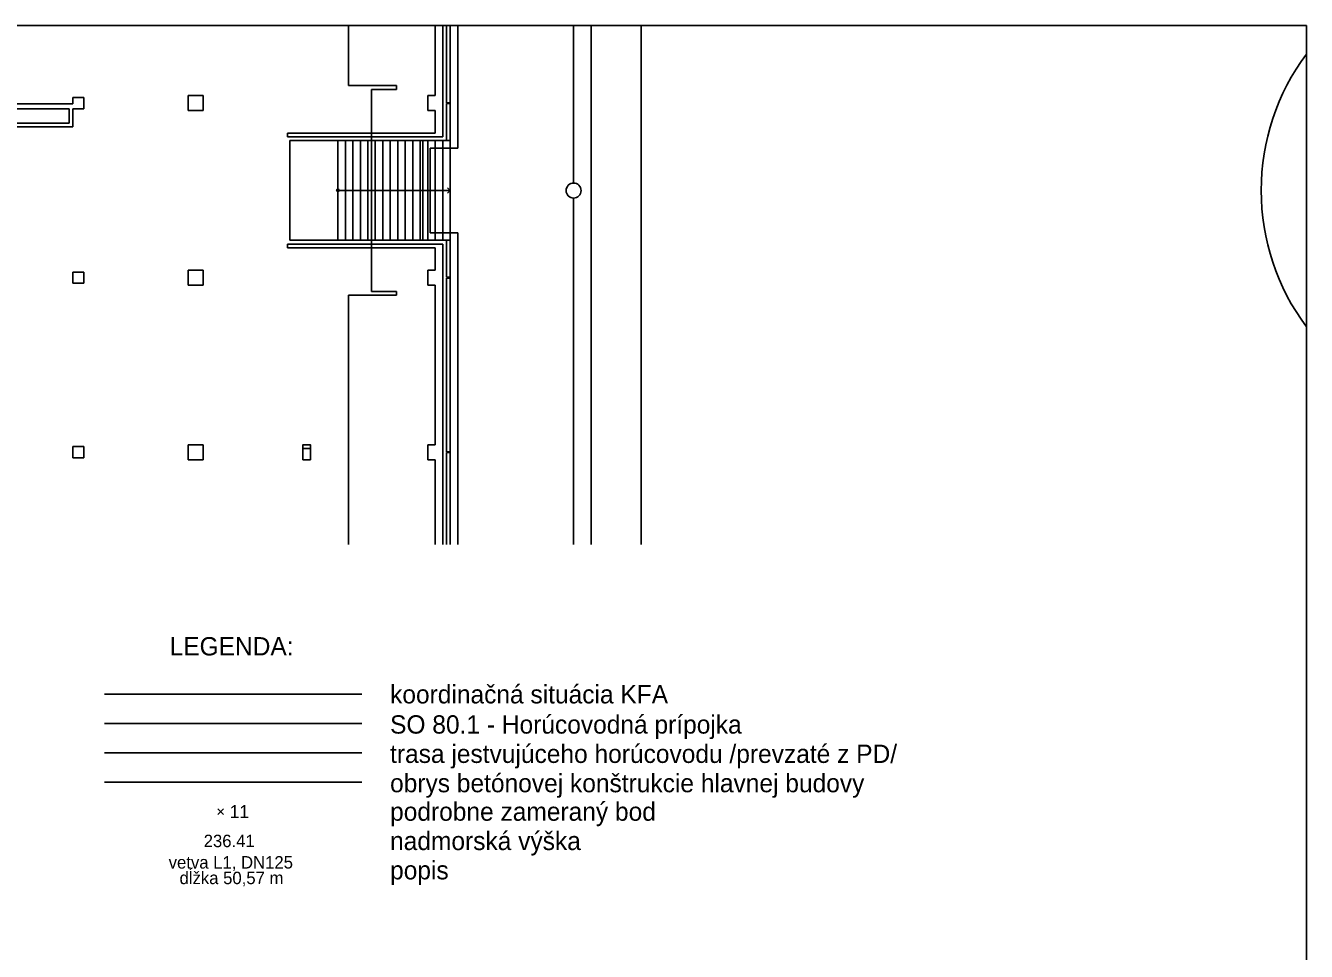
# Model space of a CAD drawing. Extents: x -263964 to -263859, y -1242287 to -1242158.
# Drawn here: x -263910.6 to -263859.3, y -1242194.9 to -1242157.8 of the extents above; entities that cross this region are included whole.
import ezdxf

# ---------------------------------------------------------------- set-up
doc = ezdxf.new("R2010")
doc.units = 0
for name, color, linetype in [('KFA_2D_SITUACIA_DSP', 7, 'Continuous'), ('KFA_BETONY_HL_B_1PP', 7, 'Continuous'), ('LEGENDA', 7, 'Continuous'), ('RAM_NA_TLAC_A3_1-250', 7, 'Continuous')]:
    doc.layers.add(name, color=color, linetype=linetype)

msp = doc.modelspace()

# ---------------------------------------------------------------- linework, layer by layer
at = {"layer": 'KFA_2D_SITUACIA_DSP'}
for p, q in [((-263897.693, -1242157.773), (-263897.693, -1242160.182)), ((-263893.618, -1242178.582), (-263893.618, -1242157.773)), ((-263893.618, -1242157.773), (-263893.618, -1242162.382)), ((-263893.618, -1242162.382), (-263893.618, -1242157.773)), ((-263893.318, -1242157.773), (-263893.318, -1242162.682)), ((-263888.673, -1242157.773), (-263888.673, -1242164.087)), ((-263887.968, -1242178.582), (-263887.968, -1242157.773)), ((-263885.968, -1242178.582), (-263885.968, -1242157.773)), ((-263897.693, -1242160.182), (-263895.768, -1242160.182)), ((-263895.768, -1242160.332), (-263896.768, -1242160.332)), ((-263896.768, -1242160.332), (-263896.768, -1242168.432)), ((-263895.768, -1242160.182), (-263895.768, -1242160.332)), ((-263900.043, -1242166.382), (-263900.043, -1242162.382)), ((-263900.043, -1242162.382), (-263893.618, -1242162.382)), ((-263898.118, -1242162.382), (-263898.118, -1242166.382)), ((-263897.818, -1242162.382), (-263897.818, -1242166.382)), ((-263897.518, -1242162.382), (-263897.518, -1242166.382)), ((-263897.218, -1242162.382), (-263897.218, -1242166.382)), ((-263896.918, -1242162.382), (-263896.918, -1242166.382)), ((-263896.618, -1242162.382), (-263896.618, -1242166.382)), ((-263896.318, -1242162.382), (-263896.318, -1242166.382)), ((-263896.018, -1242162.382), (-263896.018, -1242166.382)), ((-263895.718, -1242162.382), (-263895.718, -1242166.382)), ((-263895.418, -1242162.382), (-263895.418, -1242166.382)), ((-263895.118, -1242162.382), (-263895.118, -1242166.382)), ((-263894.818, -1242162.382), (-263894.818, -1242166.382)), ((-263893.618, -1242162.382), (-263894.718, -1242162.382)), ((-263894.718, -1242162.382), (-263894.718, -1242166.382)), ((-263894.518, -1242162.382), (-263894.518, -1242166.382)), ((-263894.218, -1242162.382), (-263894.218, -1242166.382)), ((-263893.918, -1242162.382), (-263893.918, -1242166.382)), ((-263893.618, -1242162.382), (-263893.618, -1242166.382)), ((-263893.318, -1242162.682), (-263894.418, -1242162.682)), ((-263894.418, -1242162.682), (-263894.418, -1242166.082)), ((-263898.118, -1242164.382), (-263893.618, -1242164.382)), ((-263893.618, -1242164.382), (-263893.721, -1242164.274)), ((-263893.618, -1242164.382), (-263893.721, -1242164.491)), ((-263888.673, -1242164.687), (-263888.673, -1242178.582)), ((-263894.418, -1242166.082), (-263893.318, -1242166.082)), ((-263893.318, -1242166.082), (-263893.318, -1242178.582)), ((-263893.618, -1242166.382), (-263900.043, -1242166.382)), ((-263894.718, -1242166.382), (-263893.618, -1242166.382)), ((-263893.618, -1242166.382), (-263893.618, -1242178.582)), ((-263893.618, -1242178.582), (-263893.618, -1242166.382)), ((-263895.768, -1242168.582), (-263897.693, -1242168.582)), ((-263897.693, -1242168.582), (-263897.693, -1242178.582)), ((-263896.768, -1242168.432), (-263895.768, -1242168.432)), ((-263895.768, -1242168.432), (-263895.768, -1242168.582))]:
    msp.add_line(p, q, dxfattribs=at)
for centre, radius in [((-263888.673, -1242164.387), 0.3), ((-263898.118, -1242164.382), 0.05)]:
    msp.add_circle(centre, radius, dxfattribs=at)
for start, end in [(143.329, 180), (180, 216.671)]:
    msp.add_arc((-263851.968, -1242164.382), 9.15, start, end, dxfattribs=at)
at = {"layer": 'KFA_BETONY_HL_B_1PP'}
for p, q in [((-263894.218, -1242157.773), (-263894.218, -1242160.582)), ((-263893.918, -1242157.773), (-263893.918, -1242160.582)), ((-263893.918, -1242160.582), (-263893.918, -1242157.773)), ((-263893.768, -1242157.773), (-263893.768, -1242160.867)), ((-263893.618, -1242160.867), (-263893.618, -1242157.773)), ((-263910.143, -1242160.907), (-263911.793, -1242160.907)), ((-263908.743, -1242160.907), (-263910.143, -1242160.907)), ((-263908.743, -1242160.657), (-263908.293, -1242160.657)), ((-263908.743, -1242160.907), (-263908.743, -1242160.657)), ((-263908.293, -1242160.657), (-263908.293, -1242161.107)), ((-263903.518, -1242160.582), (-263904.118, -1242160.582)), ((-263904.118, -1242161.182), (-263904.118, -1242160.582)), ((-263903.518, -1242161.182), (-263903.518, -1242160.582)), ((-263894.518, -1242160.582), (-263894.518, -1242161.182)), ((-263894.518, -1242160.582), (-263894.218, -1242160.582)), ((-263893.918, -1242161.182), (-263893.918, -1242160.582)), ((-263893.768, -1242160.867), (-263893.618, -1242160.867)), ((-263893.768, -1242160.897), (-263893.768, -1242162.382)), ((-263893.618, -1242160.897), (-263893.768, -1242160.897)), ((-263893.618, -1242162.382), (-263893.618, -1242160.897)), ((-263911.793, -1242161.107), (-263908.893, -1242161.107)), ((-263908.893, -1242161.107), (-263908.893, -1242161.687)), ((-263908.293, -1242161.107), (-263908.743, -1242161.107)), ((-263908.743, -1242161.687), (-263908.743, -1242161.107)), ((-263904.118, -1242161.182), (-263903.518, -1242161.182)), ((-263894.518, -1242161.182), (-263894.218, -1242161.182)), ((-263894.218, -1242162.082), (-263894.218, -1242161.182)), ((-263893.918, -1242161.182), (-263893.918, -1242162.232)), ((-263908.893, -1242161.687), (-263911.793, -1242161.687)), ((-263911.593, -1242161.837), (-263908.893, -1242161.837)), ((-263908.893, -1242161.837), (-263908.743, -1242161.837)), ((-263908.743, -1242161.837), (-263908.743, -1242161.687)), ((-263894.218, -1242162.082), (-263900.143, -1242162.082)), ((-263900.143, -1242162.082), (-263900.143, -1242162.232)), ((-263900.143, -1242162.232), (-263893.918, -1242162.232)), ((-263893.768, -1242162.382), (-263893.618, -1242162.382)), ((-263900.143, -1242166.532), (-263900.143, -1242166.682)), ((-263893.918, -1242166.532), (-263900.143, -1242166.532)), ((-263900.143, -1242166.682), (-263894.218, -1242166.682)), ((-263894.218, -1242166.682), (-263894.218, -1242167.582)), ((-263893.918, -1242166.532), (-263893.918, -1242168.182)), ((-263893.768, -1242166.382), (-263893.768, -1242167.867)), ((-263893.618, -1242166.382), (-263893.768, -1242166.382)), ((-263893.618, -1242167.867), (-263893.618, -1242166.382)), ((-263908.743, -1242167.657), (-263908.293, -1242167.657)), ((-263908.743, -1242168.107), (-263908.743, -1242167.657)), ((-263908.293, -1242167.657), (-263908.293, -1242168.107)), ((-263903.518, -1242167.582), (-263904.118, -1242167.582)), ((-263904.118, -1242168.182), (-263904.118, -1242167.582)), ((-263903.518, -1242168.182), (-263903.518, -1242167.582)), ((-263894.218, -1242167.582), (-263894.518, -1242167.582)), ((-263894.518, -1242167.582), (-263894.518, -1242168.182)), ((-263908.293, -1242168.107), (-263908.743, -1242168.107)), ((-263904.118, -1242168.182), (-263903.518, -1242168.182)), ((-263894.518, -1242168.182), (-263894.218, -1242168.182)), ((-263894.218, -1242168.182), (-263894.218, -1242174.582)), ((-263893.918, -1242168.182), (-263893.918, -1242174.582)), ((-263893.918, -1242168.182), (-263893.918, -1242168.182)), ((-263893.768, -1242167.867), (-263893.618, -1242167.867)), ((-263893.768, -1242167.897), (-263893.768, -1242174.867)), ((-263893.618, -1242167.897), (-263893.768, -1242167.897)), ((-263893.618, -1242174.867), (-263893.618, -1242167.897)), ((-263908.743, -1242174.657), (-263908.293, -1242174.657)), ((-263908.743, -1242175.107), (-263908.743, -1242174.657)), ((-263908.293, -1242174.657), (-263908.293, -1242175.107)), ((-263904.118, -1242175.182), (-263904.118, -1242174.582)), ((-263904.118, -1242174.582), (-263903.518, -1242174.582)), ((-263903.518, -1242175.182), (-263903.518, -1242174.582)), ((-263899.218, -1242174.732), (-263899.518, -1242174.732)), ((-263894.518, -1242174.582), (-263894.518, -1242175.182)), ((-263894.518, -1242174.582), (-263894.218, -1242174.582)), ((-263893.918, -1242178.582), (-263893.918, -1242174.582)), ((-263893.768, -1242174.867), (-263893.618, -1242174.867)), ((-263893.768, -1242174.897), (-263893.768, -1242178.582)), ((-263893.618, -1242174.897), (-263893.768, -1242174.897)), ((-263893.618, -1242178.582), (-263893.618, -1242174.897)), ((-263908.293, -1242175.107), (-263908.743, -1242175.107)), ((-263904.118, -1242175.182), (-263904.118, -1242175.182)), ((-263904.118, -1242175.182), (-263903.518, -1242175.182)), ((-263894.518, -1242175.182), (-263894.218, -1242175.182)), ((-263894.518, -1242175.182), (-263894.218, -1242175.182)), ((-263894.218, -1242178.582), (-263894.218, -1242175.182))]:
    msp.add_line(p, q, dxfattribs=at)
msp.add_lwpolyline([(-263899.218, -1242175.182), (-263899.218, -1242174.582), (-263899.518, -1242174.582), (-263899.518, -1242175.182), (-263899.218, -1242175.182)], dxfattribs=at)
at = {"layer": 'LEGENDA'}
for p, q in [((-263907.469, -1242184.588), (-263897.154, -1242184.588)), ((-263907.469, -1242185.764), (-263897.154, -1242185.764)), ((-263907.469, -1242186.94), (-263897.154, -1242186.94)), ((-263907.469, -1242188.116), (-263897.154, -1242188.116)), ((-263902.936, -1242189.407), (-263902.705, -1242189.176)), ((-263902.705, -1242189.407), (-263902.936, -1242189.176))]:
    msp.add_line(p, q, dxfattribs=at)
at = {"layer": 'RAM_NA_TLAC_A3_1-250'}
msp.add_lwpolyline([(-263964.307, -1242157.773), (-263859.307, -1242157.773), (-263859.307, -1242232.023), (-263964.307, -1242232.023)], close=True, dxfattribs=at)

# ---------------------------------------------------------------- texts
at = {"layer": 'LEGENDA'}
for s, height, p in [('LEGENDA:', 0.7348, (-263904.863, -1242183.03)), ('koordinačná situácia KFA', 0.73477, (-263896.027, -1242184.955)), ('SO 80.1 - Horúcovodná prípojka', 0.73477, (-263896.027, -1242186.165)), ('trasa jestvujúceho horúcovodu /prevzaté z PD/', 0.73477, (-263896.027, -1242187.341)), ('obrys betónovej konštrukcie hlavnej budovy', 0.73477, (-263896.027, -1242188.517)), ('11', 0.5225, (-263902.454, -1242189.553)), ('podrobne zameraný bod', 0.73477, (-263896.027, -1242189.659)), ('236.41', 0.5, (-263903.496, -1242190.718)), ('nadmorská výška', 0.73477, (-263896.027, -1242190.835)), ('vetva L1, DN125', 0.5, (-263904.899, -1242191.577)), ('popis', 0.7348, (-263896.027, -1242192.01)), ('dĺžka 50,57 m', 0.5, (-263904.464, -1242192.202))]:
    msp.add_text(s, height=height, dxfattribs=at).set_placement(p)

doc.saveas('drawing.dxf')
